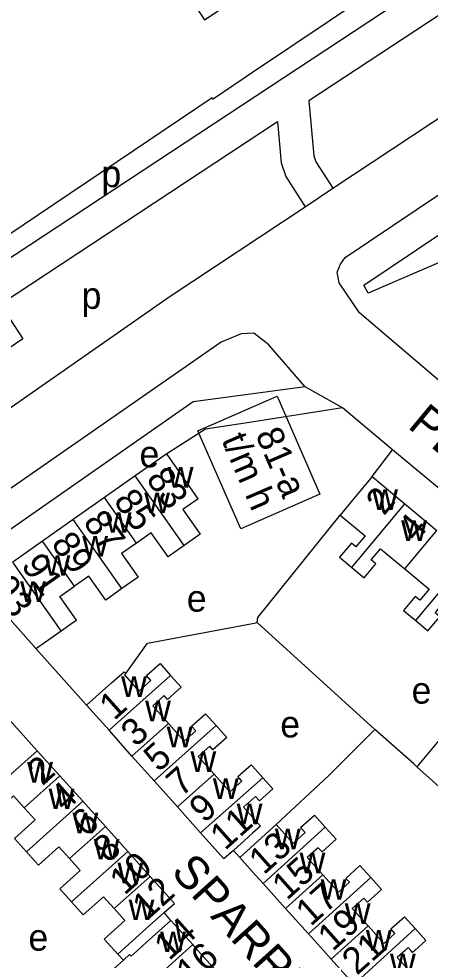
# Model space of a CAD drawing. Extents: x 158356 to 159894, y 383831 to 385260.
# Drawn here: x 159064.9 to 159126.7, y 384298.5 to 384439.8 of the extents above; entities that cross this region are included whole.
import ezdxf

# ---------------------------------------------------------------- set-up
doc = ezdxf.new("R2010")
doc.units = 0
for name, color, linetype in [('BLT_Basislijn', 7, 'Continuous'), ('BLT_Bebouwing', 7, 'Continuous'), ('BLT_Centroide', 7, 'Continuous'), ('BLT_Huisnummer', 7, 'Continuous'), ('BLT_Huisnummer_ tussenligend', 7, 'Continuous'), ('BLT_Onderverdeling_panden', 7, 'Continuous'), ('BLT_Plantopo', 7, 'Continuous'), ('BLT_Straatnaam', 7, 'Continuous')]:
    doc.layers.add(name, color=color, linetype=linetype)

msp = doc.modelspace()

# ---------------------------------------------------------------- linework, layer by layer
at = {"layer": 'BLT_Basislijn'}
for p, q in [((159112.04, 384414.39), (159153.59, 384441.97)), ((159107.88, 384411.63), (159112.04, 384414.39)), ((159113.51, 384381.42), (159107.87, 384384.6)), ((159113.51, 384381.42), (159099.51, 384379.23)), ((159120.99, 384375.14), (159113.51, 384381.42)), ((159092.9, 384378.22), (159087.09, 384374.54)), ((159099.51, 384379.23), (159092.9, 384378.22)), ((159117.95, 384371.11), (159120.99, 384375.14)), ((159100.68, 384349.24), (159118.36, 384333.16)), ((159067.46, 384345.31), (159075.07, 384336.82)), ((159138.55, 384344.25), (159124.65, 384327.57)), ((159055.98, 384342.94), (159067.65, 384329.98)), ((159124.65, 384327.57), (159150.18, 384304.55)), ((159098.06, 384313.94), (159097.1, 384315.02)), ((159087.73, 384304.51), (159086.71, 384305.68)), ((159079.74, 384299.43), (159080.61, 384298.56))]:
    msp.add_line(p, q, dxfattribs=at)
for points in [[(159145.05, 384457.61), (159060.05, 384401.58)], [(159147.89, 384453.5), (159108.45, 384427.5)], [(159113, 384400.2), (159112.71, 384401.82), (159113.18, 384402.98), (159113.91, 384403.99), (159171.01, 384442.31), (159172.55, 384442.82), (159173.83, 384442.55), (159175, 384441.52), (159176.18, 384439.75)], [(159117.37, 384398.63), (159116.7, 384399.84), (159176.18, 384439.75)], [(159108.45, 384427.5), (159109.19, 384419.27), (159109.5, 384418.36), (159112.04, 384414.39)], [(159184.34, 384427.53), (159117.37, 384398.63)], [(159103.71, 384424.37), (159062.11, 384396.95), (159065.51, 384391.8), (159022.52, 384362.59), (159020.76, 384365.2), (159002.31, 384352.75)], [(159103.71, 384424.37), (159104.26, 384418.22), (159104.96, 384416.17), (159107.88, 384411.63)], [(159009.36, 384342.67), (159052.9, 384374.04), (159087.63, 384398.19), (159107.88, 384411.63)], [(159129.92, 384383.9), (159116.07, 384395.72), (159113, 384400.2)], [(159107.87, 384384.6), (159102.42, 384390.91), (159100.16, 384392.64), (159098.26, 384392.55), (159095.28, 384391.28), (159055.69, 384363.84), (159054.64, 384361.87), (159054.93, 384359.91), (159055.85, 384357.8)], [(159107.87, 384384.6), (159091.07, 384382.35), (159055.85, 384357.8)], [(159146.62, 384353.87), (159146.2, 384354.23), (159120.99, 384375.14)], [(159100.68, 384349.24), (159100.76, 384349.99), (159113.15, 384365.34)], [(159080.95, 384341.56), (159084.2, 384346.14), (159100, 384349.08), (159100.68, 384349.24)], [(159103.55, 384318.89), (159111.48, 384326.33), (159118.36, 384333.16)], [(159124.65, 384327.57), (159124.2, 384327.99), (159118.36, 384333.16)]]:
    msp.add_lwpolyline(points, dxfattribs=at)
at = {"layer": 'BLT_Bebouwing'}
for p, q in [((159082.38, 384371.23), (159077.73, 384367.96)), ((159117.95, 384371.11), (159122.85, 384367.02)), ((159077.73, 384367.96), (159073.07, 384364.68)), ((159122.85, 384367.02), (159127.66, 384363.02)), ((159073.07, 384364.68), (159068.46, 384361.45)), ((159068.46, 384361.45), (159063.97, 384358.29)), ((159058.95, 384354.76), (159067.46, 384345.31)), ((159078.45, 384333.04), (159075.07, 384336.82)), ((159081.88, 384329.18), (159078.45, 384333.04)), ((159071.06, 384326.2), (159067.65, 384329.98)), ((159085.22, 384325.45), (159081.88, 384329.18)), ((159074.48, 384322.39), (159071.06, 384326.2)), ((159088.7, 384321.54), (159085.22, 384325.45)), ((159077.88, 384318.6), (159074.48, 384322.39)), ((159092.18, 384317.64), (159088.7, 384321.54)), ((159081.24, 384314.86), (159077.88, 384318.6)), ((159084.6, 384311.12), (159081.24, 384314.86)), ((159104.94, 384306.3), (159101.56, 384310.06)), ((159108.37, 384302.51), (159104.94, 384306.3)), ((159091.01, 384300.87), (159087.73, 384304.51)), ((159080.61, 384298.56), (159079.14, 384297.23)), ((159115.22, 384294.9), (159111.8, 384298.7))]:
    msp.add_line(p, q, dxfattribs=at)
for points in [[(159052.43, 384500), (159092.76, 384439.67), (159100, 384444.5), (159100.59, 384444.89), (159100, 384445.78), (159063.78, 384500)], [(159140.15, 384458.98), (159140.27, 384458.81), (159100, 384431.76), (159094.07, 384427.78), (159093.93, 384427.98), (159060.72, 384405.67)], [(159087.09, 384374.54), (159082.38, 384371.23)], [(159091.81, 384367.79), (159087.09, 384374.54)], [(159117.95, 384371.11), (159114.75, 384367.26), (159113.15, 384365.34)], [(159091.81, 384367.79), (159089.54, 384366.18), (159092.13, 384362.49), (159089.72, 384360.79)], [(159113.15, 384365.34), (159116.89, 384362.22), (159115.52, 384360.58), (159114.83, 384361.15), (159113.05, 384359.02), (159114.9, 384357.48)], [(159089.72, 384360.79), (159087.3, 384359.09), (159084.77, 384362.7), (159082.54, 384361.13)], [(159082.54, 384361.13), (159080.3, 384359.56), (159082.8, 384356), (159080.37, 384354.3)], [(159114.9, 384357.48), (159116.75, 384355.94), (159118.51, 384358.05), (159117.82, 384358.63), (159119.22, 384360.3), (159122.87, 384357.26)], [(159122.87, 384357.26), (159126.52, 384354.22), (159125.13, 384352.55), (159124.42, 384353.14), (159122.66, 384351.02), (159124.49, 384349.5)], [(159080.37, 384354.3), (159077.95, 384352.59), (159075.41, 384356.19), (159073.23, 384354.66)], [(159071.23, 384347.96), (159073, 384349.21), (159073.54, 384349.59), (159071.05, 384353.13), (159073.23, 384354.66)], [(159124.49, 384349.5), (159126.33, 384347.97), (159128.09, 384350.09), (159127.41, 384350.66), (159128.81, 384352.34), (159132.45, 384349.31)], [(159067.46, 384345.31), (159068.91, 384346.33), (159071.23, 384347.96)], [(159080.95, 384341.56), (159080.75, 384341.38), (159082.93, 384338.93), (159084.71, 384340.53), (159084.07, 384341.25), (159086.1, 384343.06), (159087.68, 384341.28)], [(159075.07, 384336.82), (159078.8, 384340.15), (159080.69, 384341.84), (159080.95, 384341.56)], [(159087.68, 384341.28), (159089.27, 384339.5), (159087.23, 384337.68), (159086.72, 384338.26), (159084.99, 384336.73), (159087.36, 384334.07)], [(159087.36, 384334.07), (159089.73, 384331.42), (159091.47, 384332.97), (159090.84, 384333.68), (159092.91, 384335.53), (159094.51, 384333.74)], [(159094.51, 384333.74), (159096.11, 384331.95), (159094.04, 384330.1), (159093.56, 384330.64), (159091.84, 384329.11), (159094.21, 384326.45)], [(159067.65, 384329.98), (159063.94, 384326.65), (159059.22, 384322.41)], [(159094.21, 384326.45), (159096.58, 384323.8), (159098.38, 384325.4), (159097.77, 384326.08), (159099.79, 384327.88), (159100, 384327.65), (159101.55, 384325.91)], [(159101.55, 384325.91), (159103.04, 384324.25), (159101.02, 384322.44), (159100.43, 384323.1), (159100, 384322.72), (159098.65, 384321.51), (159100, 384320), (159101.19, 384318.67), (159100, 384317.6), (159099.4, 384317.07), (159097.1, 384315.02)], [(159059.22, 384322.41), (159061, 384320.42), (159064.09, 384323.19), (159065.7, 384321.39)], [(159065.7, 384321.39), (159067.32, 384319.59), (159064.23, 384316.81), (159066.03, 384314.8)], [(159103.55, 384318.89), (159106.09, 384316.07), (159107.88, 384317.68), (159107.21, 384318.43), (159109.29, 384320.3), (159110.91, 384318.49)], [(159098.06, 384313.94), (159103.55, 384318.89)], [(159097.1, 384315.02), (159095.67, 384313.74), (159092.18, 384317.64)], [(159110.91, 384318.49), (159112.54, 384316.69), (159110.42, 384314.78), (159109.84, 384315.42), (159108.21, 384313.95), (159110.55, 384311.35)], [(159066.03, 384314.8), (159067.83, 384312.8), (159070.91, 384315.56), (159072.51, 384313.78)], [(159072.51, 384313.78), (159074.11, 384311.99), (159071.05, 384309.25), (159072.81, 384307.3)], [(159101.56, 384310.06), (159100, 384311.79), (159098.06, 384313.94)], [(159110.55, 384311.35), (159112.88, 384308.76), (159114.52, 384310.23), (159113.99, 384310.81), (159116.11, 384312.73), (159117.73, 384310.94)], [(159086.71, 384305.68), (159088.24, 384307.06), (159084.6, 384311.12)], [(159117.73, 384310.94), (159119.34, 384309.15), (159117.23, 384307.25), (159116.69, 384307.85), (159114.96, 384306.3), (159117.33, 384303.68)], [(159072.81, 384307.3), (159074.56, 384305.34), (159077.59, 384308.06), (159079.2, 384306.27)], [(159079.2, 384306.27), (159080.81, 384304.48), (159077.71, 384301.69), (159079.74, 384299.43)], [(159086.71, 384305.68), (159084.52, 384303.72), (159080.38, 384300), (159079.74, 384299.43)], [(159117.33, 384303.68), (159119.69, 384301.06), (159121.35, 384302.56), (159120.75, 384303.23), (159122.78, 384305.06), (159124.4, 384303.27)], [(159087.73, 384304.51), (159084.01, 384301.17), (159082.72, 384300), (159081.76, 384299.14), (159081.53, 384299.39), (159080.61, 384298.56)], [(159124.4, 384303.27), (159126.02, 384301.48), (159124.38, 384300), (159124.02, 384299.67), (159123.73, 384300), (159123.35, 384300.42), (159122.89, 384300), (159121.71, 384298.94), (159124.15, 384296.22)], [(159111.8, 384298.7), (159110.62, 384300), (159108.37, 384302.51)], [(159094.44, 384297.06), (159091.79, 384300), (159091.01, 384300.87)]]:
    msp.add_lwpolyline(points, dxfattribs=at)
at = {"layer": 'BLT_Onderverdeling_panden'}
for p, q in [((159089.72, 384360.79), (159082.38, 384371.23)), ((159082.54, 384361.13), (159077.73, 384367.96)), ((159114.9, 384357.48), (159122.85, 384367.02)), ((159080.37, 384354.3), (159073.07, 384364.68)), ((159122.87, 384357.26), (159127.66, 384363.02)), ((159073.23, 384354.66), (159068.46, 384361.45)), ((159071.23, 384347.96), (159063.97, 384358.29)), ((159124.49, 384349.5), (159132.44, 384359.04)), ((159087.68, 384341.28), (159078.45, 384333.04)), ((159087.36, 384334.07), (159081.88, 384329.18)), ((159094.51, 384333.74), (159085.22, 384325.45)), ((159065.7, 384321.39), (159071.06, 384326.2)), ((159094.21, 384326.45), (159088.7, 384321.54)), ((159092.18, 384317.64), (159101.55, 384325.91)), ((159066.03, 384314.8), (159074.48, 384322.39)), ((159072.51, 384313.78), (159077.88, 384318.6)), ((159110.91, 384318.49), (159101.56, 384310.06)), ((159072.81, 384307.3), (159081.24, 384314.86)), ((159079.2, 384306.27), (159084.6, 384311.12)), ((159110.55, 384311.35), (159104.94, 384306.3)), ((159117.73, 384310.94), (159108.37, 384302.51)), ((159117.33, 384303.68), (159111.8, 384298.7)), ((159124.4, 384303.27), (159115.22, 384294.9)), ((159085.78, 384296.16), (159091.01, 384300.87))]:
    msp.add_line(p, q, dxfattribs=at)
at = {"layer": 'BLT_Plantopo'}
msp.add_lwpolyline([(159091.76, 384377.99), (159103.66, 384383.21), (159110.11, 384368.49), (159098.21, 384363.27)], close=True, dxfattribs=at)

# ---------------------------------------------------------------- texts
at = {"layer": 'BLT_Centroide'}
for s, p in [('p', (159077.29, 384414.56)), ('p', (159074.31, 384396.3)), ('e', (159083.01, 384372.51)), ('w', (159087.25, 384369.47)), ('w', (159083.72, 384365.64)), ('w', (159117.95, 384366.12)), ('w', (159077.94, 384362.7)), ('w', (159122.3, 384361.47)), ('w', (159074.42, 384359.12)), ('w', (159068.75, 384356.25)), ('w', (159065.09, 384352.31)), ('e', (159090.11, 384350.85)), ('w', (159080.25, 384338.06)), ('e', (159123.87, 384337.04)), ('w', (159083.86, 384334.41)), ('e', (159104.15, 384331.97)), ('w', (159087.1, 384330.5)), ('w', (159090.66, 384326.8)), ('w', (159066.14, 384325.19)), ('w', (159094.03, 384322.75)), ('w', (159069.36, 384321.22)), ('w', (159097.61, 384318.95)), ('w', (159072.95, 384317.59)), ('w', (159103.34, 384315.19)), ('w', (159076.14, 384313.66)), ('w', (159107.05, 384311.59)), ('w', (159079.7, 384310.09)), ('w', (159110.22, 384307.62)), ('w', (159081.38, 384304.55)), ('w', (159113.84, 384303.98)), ('e', (159066.33, 384299.96)), ('w', (159086.12, 384299.75)), ('w', (159117.01, 384299.97)), ('w', (159120.62, 384296.42))]:
    msp.add_text(s, height=4, dxfattribs=at).set_placement(p)
at = {"layer": 'BLT_Huisnummer'}
for s, rotation, p in [('81-a', 293.3066, (159100.36, 384377.46)), ('t/m h', 293.3066, (159095.27, 384376.64)), ('83', 305.1212, (159083.89, 384370.76)), ('2', 50.2209, (159119.72, 384365.14)), ('87', 305.1212, (159074.44, 384364.28)), ('93', 305.1039, (159060.6, 384354.53)), ('1', 41.7437, (159079.2, 384334.4)), ('5', 41.7437, (159085.88, 384326.65)), ('2', 41.9005, (159068.41, 384324.6)), ('6', 41.9005, (159075.01, 384316.86)), ('11', 41.7437, (159095.85, 384314.9)), ('13', 41.7437, (159101.67, 384311.23)), ('12', 41.9005, (159084.17, 384304.43)), ('17', 41.7437, (159108.71, 384303.5)), ('14', 41.9005, (159087.45, 384298.36)), ('21', 41.7437, (159115.65, 384296.16))]:
    msp.add_text(s, height=4, rotation=rotation, dxfattribs=at).set_placement(p)
at = {"layer": 'BLT_Huisnummer_ tussenligend'}
for s, rotation, p in [('85', 305.1212, (159079.01, 384367.47)), ('4', 50.2209, (159124.53, 384361.13)), ('89', 305.1212, (159069.63, 384361.04)), ('91', 305.1212, (159065.13, 384357.79)), ('3', 41.7437, (159082.45, 384330.4)), ('7', 41.7437, (159089.28, 384322.94)), ('4', 41.9005, (159071.81, 384320.72)), ('9', 41.7437, (159092.72, 384318.98)), ('8', 41.9005, (159078.3, 384312.99)), ('10', 41.9005, (159080.76, 384308.18)), ('15', 41.7437, (159105.14, 384307.41)), ('19', 41.7437, (159112.01, 384299.74)), ('16', 41.9005, (159090.75, 384294.6))]:
    msp.add_text(s, height=4, rotation=rotation, dxfattribs=at).set_placement(p)
at = {"layer": 'BLT_Straatnaam'}
for s, rotation, p in [('PLAGGENSTRAAT', 320.2686, (159123.13, 384378.55)), ('SPARRENSTRAAT', 311.9587, (159087.58, 384311.68))]:
    msp.add_text(s, height=5, rotation=rotation, dxfattribs=at).set_placement(p)

doc.saveas('drawing.dxf')
